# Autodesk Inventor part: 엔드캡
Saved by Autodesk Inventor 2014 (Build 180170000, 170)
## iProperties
Created: 2026-05
Part Number: 엔드캡
Material: 일반
Document SubType Name: Modeling
Designer: dg
Density: 1 g/cm^3
Appearance: 기본값
Author: dg
Author: jhkim
Creation Date: 2026-04-23
Sending System: Autodesk Inventor 2027
Preprocessor: ST-DEVELOPER v20.1
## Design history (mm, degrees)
node "엔드캡1"
node "솔리드1"
node "기준1"
